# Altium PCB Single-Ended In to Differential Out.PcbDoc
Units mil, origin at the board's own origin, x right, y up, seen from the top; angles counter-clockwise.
Board outline 5200 x 2240 mil, 2 copper layers (Top Layer, Bottom Layer); 36 components, 9 nets, 60 pads, 12 vias.
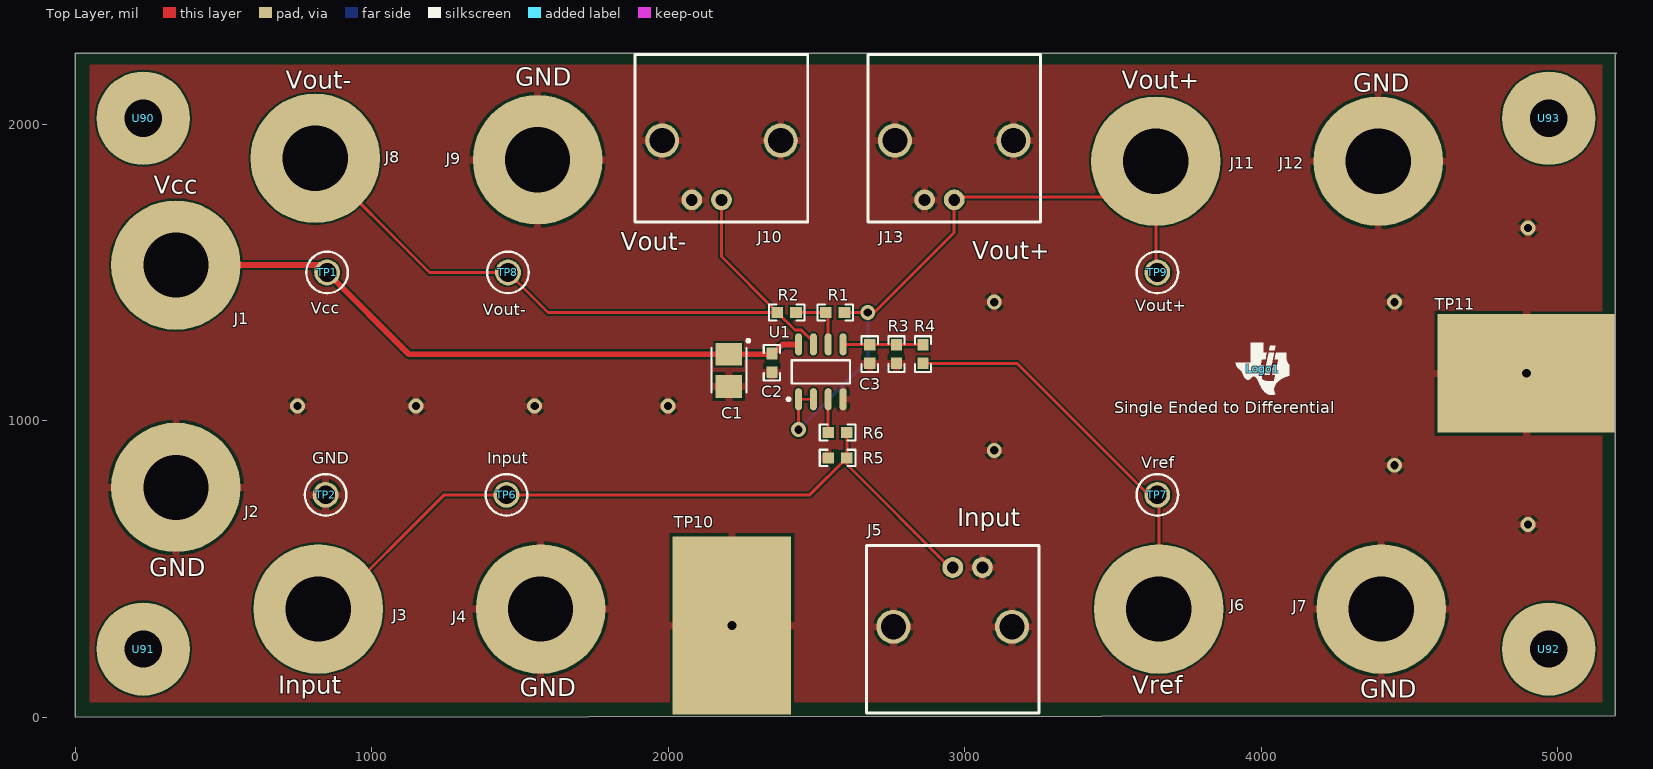
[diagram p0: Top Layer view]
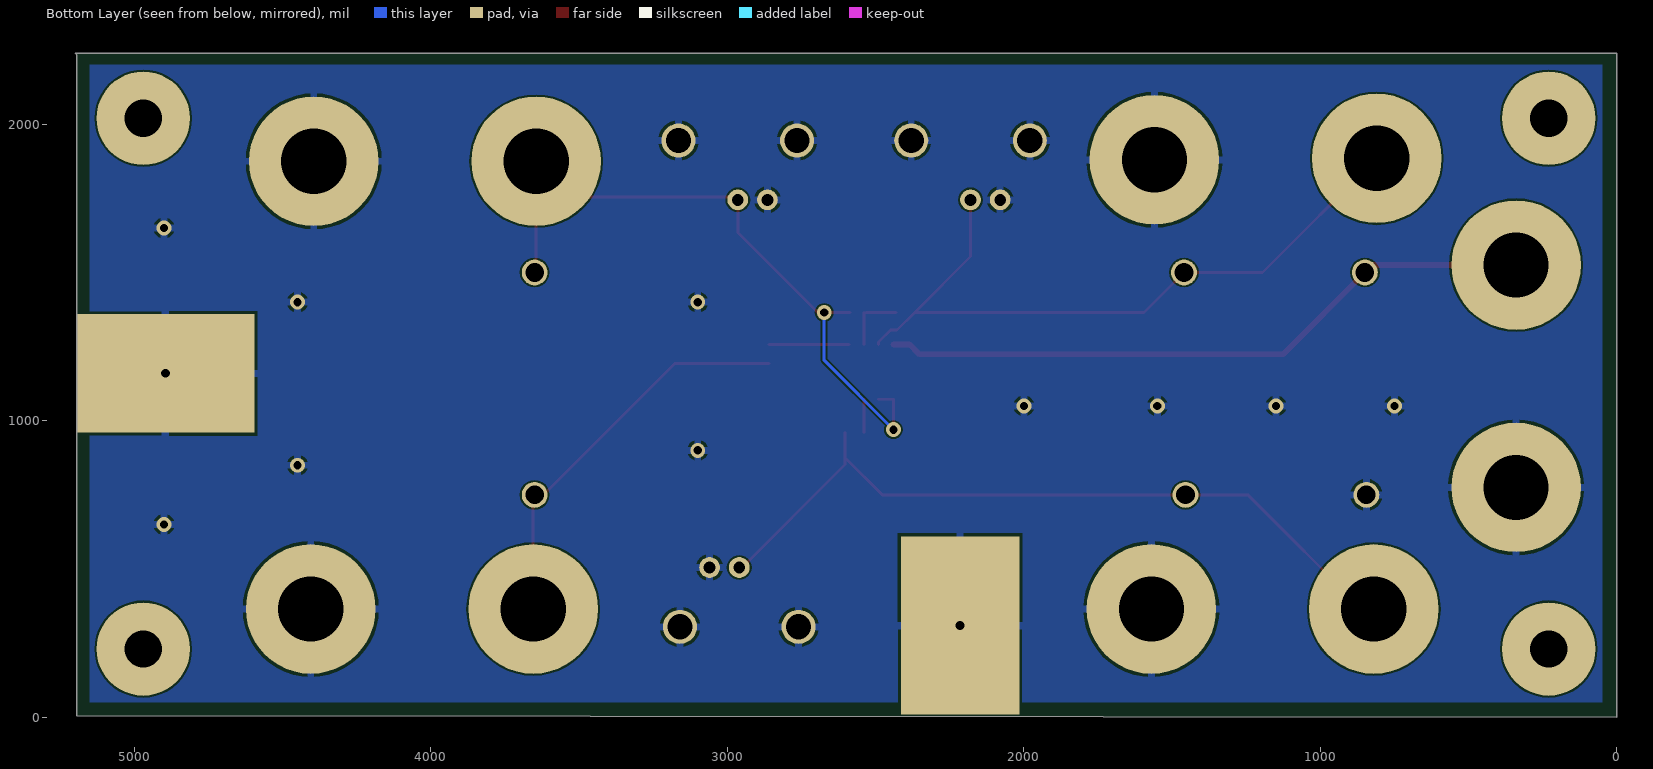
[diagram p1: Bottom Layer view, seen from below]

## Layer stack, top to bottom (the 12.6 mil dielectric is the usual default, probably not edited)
Top Layer: signal copper 1.4
Dielectric: core 12.6, FR-4, Dk 4.8
Bottom Layer: signal copper 1.4

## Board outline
0,0 0,2240 5200,2240 5195,2235 5195,5

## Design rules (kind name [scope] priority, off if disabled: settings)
AssemblyTestPointUsage [All] p1 off:
AssemblyTestpoint [All] p1 off: testpointundercomponent=TRUE minsize=40 maxsize=100 preferedsize=60 minholesize=0 maxholesize=40 preferedholesize=32 testpointgrid=1 usegrid=TRUE gridtolerance=0.01 allowsidetop=TRUE allowsidebottom=TRUE
Clearance [All] p1: gap=6
ComponentClearance [All] p1 off: gap=10 collisioncheckmode=3 verticalgap=10 showdistances=FALSE
DiffPairsRouting [All] p1 off: maxlimit=10 minlimit=10 mostfreqgap=10 maxuncoupledlength=500
FabricationTestPointUsage TestPointUsage [All] p1 off: valid=0 allowmultiple=FALSE
FabricationTestpoint Testpoint [All] p1 off: side=3 testpointundercomponent=TRUE minsize=40 maxsize=100 preferedsize=60 minholesize=0 maxholesize=40 preferedholesize=32 testpointgrid=1 allowsidetop=TRUE allowsidebottom=TRUE usegrid=TRUE gridtolerance=0.01
FanoutControl Fanout_BGA [IsBGA] p1 off: bgadir=Out bgaviamode=Centered fanoutstyle=Auto fanoutdirection=Alternating viagrid=1 // Fanout_BGA (Default Rule)
FanoutControl Fanout_LCC [IsLCC] p2 off: bgadir=Out bgaviamode=Centered fanoutstyle=Auto fanoutdirection=Alternating viagrid=1 // Fanout_LCC (Default Rule)
FanoutControl Fanout_SOIC [IsSOIC] p3 off: bgadir=Out bgaviamode=Centered fanoutstyle=Auto fanoutdirection=Alternating viagrid=1 // Fanout_SOIC (Default Rule)
FanoutControl Fanout_Small [(CompPinCount < 5)] p4 off: bgadir=Out bgaviamode=Centered fanoutstyle=Auto fanoutdirection=OutThenIn viagrid=1 // Fanout_Small (Default Rule)
FanoutControl Fanout_Default [All] p5 off: bgadir=Out bgaviamode=Centered fanoutstyle=Auto fanoutdirection=Alternating viagrid=1 // Fanout_Default (Default Rule)
Height [All] p1 off: minheight=0 maxheight=1000 prefheight=500
HoleSize [All] p1: absolutevalues=TRUE maxlimit=400 minlimit=15 maxpercent=80.000 minpercent=20.000
HoleToHoleClearance [All] p1: gap=8 allowstackedmicrovias=TRUE
LayerPairs [All] p1 off: enforce=FALSE
MinimumSolderMaskSliver [All] p1: minsoldermaskwidth=4
PolygonConnect [All] p1: connectstyle=Relief reliefconductorwidth=25 reliefentries=4 polygonreliefangle="90 Angle" airgapwidth=10
RoutingVias [All] p1: holewidth=15 width=25 viastyle="Through Hole" minholewidth=15 minwidth=25 maxholewidth=400 maxwidth=500
SilkToSilkClearance [All] p1: silktosilkclearance=5
SilkscreenOverComponentPads [All] p1: minsilkscreentomaskgap=5
SolderMaskExpansion [All] p1: expansion=2
Width [All] p1: maxlimit=100 minlimit=6 preferedwidth=10
10 further rules are at their usual default settings.

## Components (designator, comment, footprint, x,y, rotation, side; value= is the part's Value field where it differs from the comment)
C1 "TPSB106M020R1000" 3528-21 2205,1170 r270 top
C2 "GRM188R71H104KA93D" 0603 2350,1195 r90 top
C3 "GRM188R71H104KA93D" 0603 2680,1225 r270 top
J1 "Vcc" "JACK NON-INSULATED .218\"" 340,1525 r90 top
J2 "GND" "JACK NON-INSULATED .218\"" 340,775 r90 top
J3 "Input" "JACK NON-INSULATED .218\"" 820,365 r90 top
J4 "GND" "JACK NON-INSULATED .218\"" 1570,365 r90 top
J5 "Input" "Right Angle BNC" 2960,505 r180 top
J6 "Vref" "JACK NON-INSULATED .218\"" 3655,365 r90 top
J7 "GND" "JACK NON-INSULATED .218\"" 4405,365 r90 top
J8 "Vout-" "JACK NON-INSULATED .218\"" 810,1885 r90 top
J9 "GND" "JACK NON-INSULATED .218\"" 1560,1880 r90 top
J10 "Vout-" "Right Angle BNC" 2180,1745 r0 top
J11 "Vout+" "JACK NON-INSULATED .218\"" 3645,1875 r90 top
J12 "GND" "JACK NON-INSULATED .218\"" 4395,1875 r90 top
J13 "Vout+" "Right Angle BNC" 2965,1745 r0 top
Logo1 "Single Ended to Differential" TI_Symbol_Overlay_Small 4005,1175 r0 top
R1 "49.9k" 0603 2563.62,1365 r180 top
R2 "CRCW06031K00FKEA" 0603 2400,1365 r180 top
R3 "CRCW06031K00FKEA" 0603 2770,1225 r90 top
R4 "1k00" 0603 2860,1225 r90 top
R5 "RC0603FR-0710KL" 0603 2571.5,875 r0 top
R6 "RC0603FR-0710KL" 0603 2571.5,960 r180 top
TP1 "Vcc" Keystone5005 850,1500 r90 top
TP2 "GND" Keystone5006 845,750 r90 top
TP6 "Input" Keystone5009 1455,750 r90 top
TP7 "Vref" Keystone5009 3650,750 r90 top
TP8 "Vout-" Keystone5009 1460,1500 r90 top
TP9 "Vout+" Keystone5009 3650,1500 r90 top
TP10 "Scope Probe" "tg pad" 2215,310 r0 top
TP11 "Scope Probe" "tg pad" 4895,1160 r90 top
U1 "OPA2333" M08A_L 2515,1165 r90 top
U90 "NY PMS 440 0025 PH" "NY PMS 440 0025 PH" 230,2020 r0 top
U91 "NY PMS 440 0025 PH" "NY PMS 440 0025 PH" 230,230 r0 top
U92 "NY PMS 440 0025 PH" "NY PMS 440 0025 PH" 4970,230 r0 top
U93 "NY PMS 440 0025 PH" "NY PMS 440 0025 PH" 4970,2020 r0 top

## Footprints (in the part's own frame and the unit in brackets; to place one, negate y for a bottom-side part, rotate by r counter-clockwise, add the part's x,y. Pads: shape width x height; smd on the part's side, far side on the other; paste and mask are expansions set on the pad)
0603 [mm] "0603 from SM-752 data"
  rect 1x0.95 smd: 1(-0.8,0) 2(0.8,0)
  silkscreen extent -1.52,-0.69 1.52,0.69, body extent -0.87,-0.47 0.87,0.47, height 0.85
3528-21 [mm] "Medium Density IPC, based on SM-782 section 8.4"
  rect 1.95x2.25 smd: 1(-1.375,0) 2(1.375,0)
  silkscreen extent -2.66,-1.5 1.9,1.79, body extent -1.85,-1.5 1.85,1.5, height 2.1
"JACK NON-INSULATED .218\"" [mil] "JACK NON-INSULATED .218\""
  round 437 hole 220: 1(0,0)
Keystone5005 [mil] "Keystone Compact loops"
  round 87 hole 63: 1(0,0)
  silkscreen extent -70,-70 70,70, body extent -63,-63 62,63, height 225
Keystone5006 [mil] "Keystone Compact loops"
  round 87 hole 63: 1(0,0)
  silkscreen extent -70,-70 70,70, body extent -63,-63 62,63, height 225
Keystone5009 [mil] "Keystone Compact loops"
  round 87 hole 63: 1(0,0)
  silkscreen extent -70,-70 70,70, body extent -63,-63 62,63, height 225
M08A_L [mm] "SOIC, 8-Leads, Body 4.9x3.9mm, Pitch 1.27mm, IPC High Density"
  oval 1.9x0.6 smd: 1(-2.35,1.905) 2(-2.35,0.635) 3(-2.35,-0.635) 4(-2.35,-1.905) 5(2.35,-1.905) 6(2.35,-0.635) 7(2.35,0.635) 8(2.35,1.905)
  silkscreen extent -2.47,-2.5 1,2.88, body extent -2,-2.5 2,2.5, height 1.75
"NY PMS 440 0025 PH" [mm] "4-40 nylon screw and mounting hole"
  round 8 hole 3.2: 1(0,0)
  body extent -3.3,-3.3 3.3,3.3, height 2.69
"Right Angle BNC" [mil]
  round 70 hole 40: 1(0,0) 2(-100,0)
  round 115 hole 85: 3(200,200) 4(-200,200)
  silkscreen extent -291,-75 291,490, body extent -290,-50 291,1325, height 519
"tg pad" [mil] "test points for scope probes"
  rect 400x600 hole 30: 0(0,0)
TI_Symbol_Overlay_Small [mil]
  silkscreen extent -90,-88 91,88

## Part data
C1: "CAP, TANT, 10uF, 20V, +/-20%, 1 ohm, 3528-21 SMD"
C2 C3: "CAP, CERM, 0.1uF, 50V, +/-10%, X7R, 0603"
J1 J2 J3 J4 J6 J7 J8 J9 J11 J12: library part "Banana Jack, Solder", "JACK NON-INSULATED .218\""
J5 J10 J13: library part "BNC Right Angle"
Logo1: library part TI_Logo, "Texas Instrument Corporate Signature"
R1 R4: library part CRCW06031K00FKEA, "RES, 1.00k ohm, 1%, 0.1W, 0603"
R2 R3: "RES, 1.00k ohm, 1%, 0.1W, 0603"
R5 R6: "RES, 10.0k ohm, 1%, 0.1W, 0603"
TP1: library part 5005, "Test Point, TH, Compact, Red"
TP2: library part 5006, "Test Point, TH, Compact, Black"
TP6 TP7 TP8 TP9: library part 5009, "Test Point, TH, Compact, Yellow"
TP10 TP11: library part "tg pad"
U1: "Wide Bandwidth Dual JFET Input Op Amp"
U90 U91 U92 U93: "Machine Screw, Round, #4-40 x 1/4, Nylon, Philips panhead"

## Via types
v1: diameter 50, hole 28, Top Layer to Bottom Layer, 12 vias

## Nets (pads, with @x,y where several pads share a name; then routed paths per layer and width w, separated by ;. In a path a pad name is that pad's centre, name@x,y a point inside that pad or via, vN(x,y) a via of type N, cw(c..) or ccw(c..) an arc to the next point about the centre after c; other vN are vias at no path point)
GND: C1.2 C2.1 C3.2 J2.1 J4.1 J5.2 J5.3 J5.4 J7.1 J9.1 J10.2 J10.3 J10.4 J12.1 J13.2 J13.3 J13.4 R3.1 R5.1 TP2.1 TP10.0 TP11.0 U1.4
  other v1: 4900,650 4450,850 3100,900 750,1050 1150,1050 1550,1050 2000,1050 3100,1400 4450,1400 4900,1650
NetC3_1: C3.1 R3.2 R4.2 U1.5 | length 269
  Top Layer w10: U1.5 C3.1@2678.98,1257.52 ; C3.1 R4.2
NetJ3_1: J3.1 J5.1 R5.2 R6.1 TP6.1 | length 2607.1
  Top Layer w10: J3.1 860,365 1245,750 TP6.1 2477.99,750 R5.2 ; R6.1 R5.2 ; J5.1@2960,495 2602.99,852.01 R5.2
NetJ6_1: J6.1 R4.1 TP7.1 | length 1360.8
  Top Layer w10: R4.1 3176.5,1193.5 3620,750 TP7.1 3655,745 J6.1
NetJ8_1: J8.1 J10.1 R2.2 TP8.1 U1.7 | length 2412.6
  Top Layer w10: J8.1 1195,1500 TP8.1 1595,1365 R2.2 ; J10.1@2180,1755 J10.1 2180,1553.5 R2.2 ; U1.7 2490,1265.37 2449.45,1305.92 2427.58,1305.92 R2.2
NetJ11_1: J11.1 J13.1 R1.1 TP9.1 U1.1 U1.2 | length 2353.5
  Top Layer w10: v1(2440,970) U1.1 U1.2 ; R1.1@2587.24,1365 R1.1 v1(2673.62,1365) 2695,1365 2965,1635 2965,1755 3525,1755 J11.1 TP9.1@3645,1505
  Bottom Layer w10: v1(2440,970) 2673.62,1203.62 v1(2673.62,1365)
NetR1_2: R1.2 R2.1 U1.6 | length 208.1
  Top Layer w10: R2.1 R1.2 ; U1.6 R1.2@2540,1365
NetR6_2: R6.2 U1.3 | length 112.5
  Top Layer w10: R6.2 U1.3
VCC: C1.1 C2.2 J1.1 TP1.1 U1.8 | length 2238.5
  Top Layer w20: J1.1 825,1525 TP1.1 1125.87,1224.13 C1.1 2352.64,1224.13 2386.02,1257.52 U1.8
pads on no net: U90.1 U91.1 U92.1 U93.1

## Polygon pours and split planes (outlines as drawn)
GND on Bottom Layer "Top Layer-No Net" (solid, pour order 4): 50,2200 5150,2200 5150,50 50,50
GND on Top Layer "Top Layer-No Net" (solid, pour order 6): 50,50 50,2200 5150,2200 5150,50

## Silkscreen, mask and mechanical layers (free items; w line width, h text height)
Board Outline:
  lines w10: 0.91,2290.99 0.91,2310.99 ; 60.91,2280.99 0.91,2300.99 ; 60.91,2320.99 0.91,2300.99 ; 2320,2300.99 0.91,2300.99 ; 2881.83,2300.99 5200.91,2300.99 ; 5140.91,2280.99 5200.91,2300.99 ; 5140.91,2320.99 5200.91,2300.99 ; 5200.91,2290.99 5200.91,2310.99 ; 5359.01,58.41 5379.01,-1.59 ; 5359.01,2173.41 5379.01,2233.41 ; 5369.01,-1.59 5389.01,-1.59 ; 5369.01,2233.41 5389.01,2233.41 ; 5379.01,835 5379.01,-1.59 ; 5379.01,1396.83 5379.01,2233.41 ; 5399.01,58.41 5379.01,-1.59 ; 5399.01,2173.41 5379.01,2233.41 ; 0,5 5200,5 5200,2240 0,2240 0,5
  text "5200 (mil)" at 2330,2265 h60
  text "2235 (mil)" at 5415,845 h60 r90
